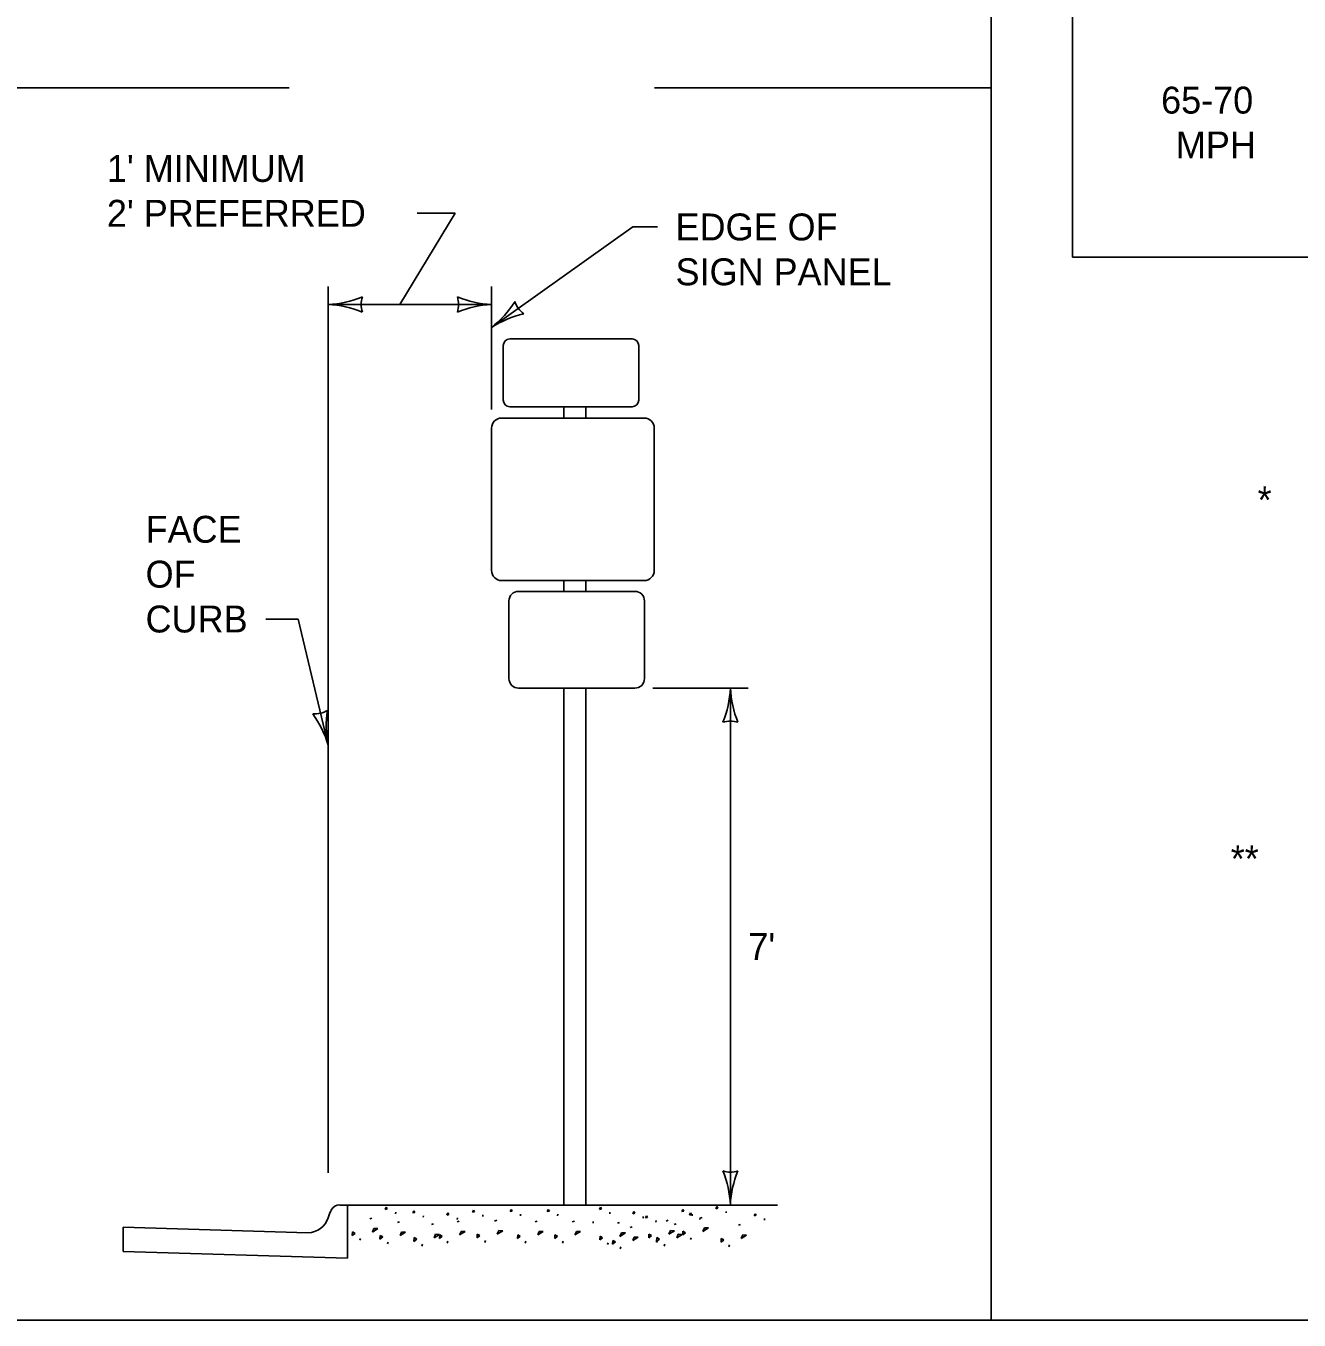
# Model space of a CAD drawing. Extents: x 49991.4 to 50021, y 49987.6 to 50011.4.
# Drawn here: x 50005.916 to 50008.753, y 49987.799 to 49990.684 of the extents above; entities that cross this region are included whole.
import ezdxf

# ---------------------------------------------------------------- set-up
doc = ezdxf.new("R2010")
doc.units = 0
for name, color, linetype in [('Level 1', 7, 'Continuous'), ('Level 2', 7, 'Continuous'), ('Level 3', 7, 'Continuous')]:
    doc.layers.add(name, color=color, linetype=linetype)

msp = doc.modelspace()

# ---------------------------------------------------------------- linework, layer by layer
at = {"layer": 'Level 1'}
for p, q in [((50006.9943, 49989.9861), (50007.2664, 49989.9861)), ((50006.9793, 49989.8499), (50006.9793, 49989.9711)), ((50007.2814, 49989.9711), (50007.2814, 49989.8499)), ((50007.2664, 49989.8349), (50006.9943, 49989.8349)), ((50007.1148, 49989.8098), (50007.1148, 49989.8349)), ((50007.1634, 49989.8098), (50007.1634, 49989.8349)), ((50006.9534, 49989.4698), (50006.9534, 49989.7873)), ((50006.9759, 49989.8098), (50007.2935, 49989.8098)), ((50007.316, 49989.7873), (50007.316, 49989.4698)), ((50007.2935, 49989.4473), (50006.9759, 49989.4473)), ((50007.1148, 49989.4234), (50007.1148, 49989.4473)), ((50007.1634, 49989.4234), (50007.1634, 49989.4473)), ((50007.0136, 49989.4234), (50007.2728, 49989.4234)), ((50006.9921, 49989.229), (50006.9921, 49989.4019)), ((50007.2943, 49989.4019), (50007.2943, 49989.229)), ((50007.2728, 49989.2075), (50007.0136, 49989.2075)), ((50007.1148, 49988.0554), (50007.1148, 49989.2075)), ((50007.1634, 49988.0554), (50007.1634, 49989.2075)), ((50006.6326, 49988.0554), (50006.6156, 49988.0554)), ((50006.6326, 49988.0554), (50007.5908, 49988.0554)), ((50006.6326, 49987.9369), (50006.6326, 49988.0554)), ((50007.4531, 49988.0472), (50007.4551, 49988.0519)), ((50007.4551, 49988.0519), (50007.4575, 49988.0483)), ((50006.6866, 49988.0261), (50006.682, 49988.0245)), ((50006.7165, 49988.0456), (50006.7186, 49988.0503)), ((50006.721, 49988.0467), (50006.7165, 49988.0456)), ((50006.7186, 49988.0503), (50006.721, 49988.0467)), ((50006.7394, 49988.036), (50006.7399, 49988.0396)), ((50006.7781, 49988.0376), (50006.7802, 49988.0423)), ((50006.7826, 49988.0387), (50006.7781, 49988.0376)), ((50006.7802, 49988.0423), (50006.7826, 49988.0387)), ((50006.8011, 49988.028), (50006.8015, 49988.0316)), ((50006.8541, 49988.0328), (50006.8561, 49988.0376)), ((50006.8585, 49988.0339), (50006.8541, 49988.0328)), ((50006.8561, 49988.0376), (50006.8585, 49988.0339)), ((50006.877, 49988.0233), (50006.8775, 49988.0269)), ((50006.9109, 49988.0393), (50006.913, 49988.044)), ((50006.9154, 49988.0404), (50006.9109, 49988.0393)), ((50006.913, 49988.044), (50006.9154, 49988.0404)), ((50006.9339, 49988.0297), (50006.9343, 49988.0333)), ((50006.9947, 49988.0409), (50006.9968, 49988.0456)), ((50006.9992, 49988.0419), (50006.9947, 49988.0409)), ((50006.9968, 49988.0456), (50006.9992, 49988.0419)), ((50007.0177, 49988.0313), (50007.0181, 49988.0349)), ((50007.0777, 49988.0409), (50007.0798, 49988.0456)), ((50007.0822, 49988.0419), (50007.0777, 49988.0409)), ((50007.0798, 49988.0456), (50007.0822, 49988.0419)), ((50007.1007, 49988.0313), (50007.1011, 49988.0349)), ((50007.1939, 49988.0456), (50007.1959, 49988.0503)), ((50007.1984, 49988.0467), (50007.1939, 49988.0456)), ((50007.1959, 49988.0503), (50007.1984, 49988.0467)), ((50007.2168, 49988.036), (50007.2173, 49988.0396)), ((50007.2682, 49988.036), (50007.2703, 49988.0407)), ((50007.2727, 49988.0371), (50007.2682, 49988.036)), ((50007.2703, 49988.0407), (50007.2727, 49988.0371)), ((50007.2912, 49988.0264), (50007.2916, 49988.0301)), ((50007.2966, 49988.0265), (50007.2987, 49988.0313)), ((50007.3011, 49988.0276), (50007.2966, 49988.0265)), ((50007.2987, 49988.0313), (50007.3011, 49988.0276)), ((50007.3773, 49988.0409), (50007.3793, 49988.0456)), ((50007.3817, 49988.0419), (50007.3773, 49988.0409)), ((50007.3793, 49988.0456), (50007.3817, 49988.0419)), ((50007.3946, 49988.0328), (50007.3967, 49988.0376)), ((50007.3991, 49988.0339), (50007.3946, 49988.0328)), ((50007.3967, 49988.0376), (50007.3991, 49988.0339)), ((50007.4002, 49988.0313), (50007.4007, 49988.0349)), ((50007.4175, 49988.0233), (50007.418, 49988.0269)), ((50007.4231, 49988.0276), (50007.4185, 49988.0261)), ((50007.4575, 49988.0483), (50007.4531, 49988.0472)), ((50007.476, 49988.0376), (50007.4765, 49988.0412)), ((50007.5384, 49988.0313), (50007.5405, 49988.036)), ((50007.5429, 49988.0324), (50007.5384, 49988.0313)), ((50007.5405, 49988.036), (50007.5429, 49988.0324)), ((50007.5614, 49988.0217), (50007.5618, 49988.0253)), ((50006.5443, 49987.9937), (50006.1327, 49988.006)), ((50006.1327, 49988.006), (50006.1327, 49987.9518)), ((50006.6429, 49987.9871), (50006.6434, 49987.9954)), ((50006.6434, 49987.9954), (50006.6492, 49987.9921)), ((50006.6912, 49988.003), (50006.6879, 49987.9951)), ((50006.6879, 49987.9951), (50006.7, 49988.0028)), ((50006.7, 49988.0028), (50006.6912, 49988.003)), ((50006.7482, 49988.0181), (50006.7436, 49988.0165)), ((50006.7528, 49987.995), (50006.7495, 49987.9871)), ((50006.7495, 49987.9871), (50006.7616, 49987.9948)), ((50006.7616, 49987.9948), (50006.7528, 49987.995)), ((50006.8241, 49988.0133), (50006.8195, 49988.0117)), ((50006.881, 49988.0197), (50006.8764, 49988.0182)), ((50006.8856, 49987.9967), (50006.8823, 49987.9888)), ((50006.8823, 49987.9888), (50006.8944, 49987.9965)), ((50006.8944, 49987.9965), (50006.8856, 49987.9967)), ((50006.9648, 49988.0213), (50006.9602, 49988.0197)), ((50006.9694, 49987.9983), (50006.9661, 49987.9904)), ((50006.9661, 49987.9904), (50006.9782, 49987.998)), ((50006.9782, 49987.998), (50006.9694, 49987.9983)), ((50007.0549, 49988.0197), (50007.0503, 49988.0182)), ((50007.0595, 49987.9967), (50007.0562, 49987.9888)), ((50007.0562, 49987.9888), (50007.0684, 49987.9965)), ((50007.0684, 49987.9965), (50007.0595, 49987.9967)), ((50007.1379, 49988.0197), (50007.1333, 49988.0182)), ((50007.1425, 49987.9967), (50007.1392, 49987.9888)), ((50007.1392, 49987.9888), (50007.1514, 49987.9965)), ((50007.1514, 49987.9965), (50007.1425, 49987.9967)), ((50007.1797, 49988.0151), (50007.1801, 49988.0187)), ((50007.2383, 49988.0165), (50007.2337, 49988.0149)), ((50007.2429, 49987.9934), (50007.2396, 49987.9855)), ((50007.2396, 49987.9855), (50007.2517, 49987.9932)), ((50007.2517, 49987.9932), (50007.2429, 49987.9934)), ((50007.2667, 49988.007), (50007.262, 49988.0054)), ((50007.3195, 49988.017), (50007.32, 49988.0206)), ((50007.3473, 49988.0213), (50007.3427, 49988.0197)), ((50007.3519, 49987.9983), (50007.3486, 49987.9904)), ((50007.3486, 49987.9904), (50007.3608, 49987.998)), ((50007.3608, 49987.998), (50007.3519, 49987.9983)), ((50007.3646, 49988.0133), (50007.36, 49988.0117)), ((50007.3794, 49987.9887), (50007.3799, 49987.9969)), ((50007.3857, 49987.9937), (50007.3794, 49987.9887)), ((50007.3799, 49987.9969), (50007.3857, 49987.9937)), ((50007.4277, 49988.0046), (50007.4244, 49987.9967)), ((50007.4244, 49987.9967), (50007.4366, 49988.0043)), ((50007.4366, 49988.0043), (50007.4277, 49988.0046)), ((50007.5085, 49988.0117), (50007.5039, 49988.0102)), ((50006.6492, 49987.9921), (50006.6429, 49987.9871)), ((50006.6617, 49987.9809), (50006.6601, 49987.9767)), ((50006.7045, 49987.9791), (50006.705, 49987.9874)), ((50006.7108, 49987.9841), (50006.7045, 49987.9791)), ((50006.705, 49987.9874), (50006.7108, 49987.9841)), ((50006.7233, 49987.9729), (50006.7217, 49987.9687)), ((50006.7804, 49987.9744), (50006.7809, 49987.9826)), ((50006.7867, 49987.9794), (50006.7804, 49987.9744)), ((50006.7809, 49987.9826), (50006.7867, 49987.9794)), ((50006.7992, 49987.9682), (50006.7977, 49987.964)), ((50006.8287, 49987.9903), (50006.8254, 49987.9824)), ((50006.8254, 49987.9824), (50006.8376, 49987.99)), ((50006.8376, 49987.99), (50006.8287, 49987.9903)), ((50006.8373, 49987.9808), (50006.8378, 49987.9891)), ((50006.8436, 49987.9858), (50006.8373, 49987.9808)), ((50006.8378, 49987.9891), (50006.8436, 49987.9858)), ((50006.8561, 49987.9746), (50006.8545, 49987.9704)), ((50006.9211, 49987.9824), (50006.9216, 49987.9906)), ((50006.9274, 49987.9874), (50006.9211, 49987.9824)), ((50006.9216, 49987.9906), (50006.9274, 49987.9874)), ((50006.9399, 49987.9762), (50006.9383, 49987.972)), ((50007.0112, 49987.9808), (50007.0117, 49987.9891)), ((50007.0175, 49987.9858), (50007.0112, 49987.9808)), ((50007.0117, 49987.9891), (50007.0175, 49987.9858)), ((50007.03, 49987.9746), (50007.0285, 49987.9704)), ((50007.0942, 49987.9808), (50007.0947, 49987.9891)), ((50007.1005, 49987.9858), (50007.0942, 49987.9808)), ((50007.0947, 49987.9891), (50007.1005, 49987.9858)), ((50007.113, 49987.9746), (50007.1115, 49987.9704)), ((50007.1946, 49987.9775), (50007.1951, 49987.9858)), ((50007.2009, 49987.9825), (50007.1946, 49987.9775)), ((50007.1951, 49987.9858), (50007.2009, 49987.9825)), ((50007.2134, 49987.9714), (50007.2118, 49987.9671)), ((50007.223, 49987.9681), (50007.2235, 49987.9763)), ((50007.2293, 49987.9731), (50007.223, 49987.9681)), ((50007.2235, 49987.9763), (50007.2293, 49987.9731)), ((50007.2713, 49987.984), (50007.268, 49987.9761)), ((50007.268, 49987.9761), (50007.2801, 49987.9837)), ((50007.2801, 49987.9837), (50007.2713, 49987.984)), ((50007.3036, 49987.9824), (50007.3041, 49987.9906)), ((50007.3099, 49987.9874), (50007.3036, 49987.9824)), ((50007.3041, 49987.9906), (50007.3099, 49987.9874)), ((50007.3224, 49987.9762), (50007.3209, 49987.972)), ((50007.321, 49987.9744), (50007.3215, 49987.9826)), ((50007.3273, 49987.9794), (50007.321, 49987.9744)), ((50007.3215, 49987.9826), (50007.3273, 49987.9794)), ((50007.3398, 49987.9682), (50007.3382, 49987.964)), ((50007.3693, 49987.9903), (50007.366, 49987.9824)), ((50007.366, 49987.9824), (50007.3781, 49987.99)), ((50007.3781, 49987.99), (50007.3693, 49987.9903)), ((50007.3982, 49987.9825), (50007.3967, 49987.9783)), ((50007.4648, 49987.9728), (50007.4653, 49987.9811)), ((50007.4711, 49987.9778), (50007.4648, 49987.9728)), ((50007.4653, 49987.9811), (50007.4711, 49987.9778)), ((50007.4836, 49987.9666), (50007.482, 49987.9624)), ((50007.5131, 49987.9887), (50007.5098, 49987.9808)), ((50007.5098, 49987.9808), (50007.5219, 49987.9885)), ((50007.5219, 49987.9885), (50007.5131, 49987.9887)), ((50006.1327, 49987.9518), (50006.6326, 49987.9369)), ((50007.2418, 49987.9619), (50007.2402, 49987.9577))]:
    msp.add_line(p, q, dxfattribs=at)
msp.add_lwpolyline([(49999.3835, 49998.9992), (50016.7501, 49998.9992), (50016.7501, 49987.7988), (49999.3835, 49987.7988)], close=True, dxfattribs=at)
for centre, radius, start, end in [((50006.9943, 49989.9711), 0.015, 90, 180), ((50007.2664, 49989.9711), 0.015, 0, 90), ((50006.9943, 49989.8499), 0.015, 180, 270), ((50007.2664, 49989.8499), 0.015, 270, 0), ((50006.9759, 49989.7873), 0.0225, 90, 180), ((50007.2935, 49989.7873), 0.0225, 0, 90), ((50006.9759, 49989.4698), 0.0225, 180, 270), ((50007.2935, 49989.4698), 0.0225, 270, 0), ((50007.0136, 49989.4019), 0.0215, 90, 180), ((50007.2728, 49989.4019), 0.0215, 0, 90), ((50007.0136, 49989.229), 0.0215, 180, 270), ((50007.2728, 49989.229), 0.0215, 270, 0), ((50006.614, 49988.0361), 0.0194, 85.2999, 156.6889), ((50006.5439, 49988.0414), 0.0477, 270.4937, 342.4535), ((50006.6403, 49988.0161), 0.0521, 148.3066, 167.8949)]:
    msp.add_arc(centre, radius, start, end, dxfattribs=at)
at = {"layer": 'Level 2'}
for p, q in [((50008.2479, 49993.5684), (50008.2479, 49990.1684)), ((50008.2479, 49990.1684), (50013.0279, 49990.1684))]:
    msp.add_line(p, q, dxfattribs=at)
at = {"layer": 'Level 3'}
for p, q in [((50008.0668, 49994.0732), (50008.0668, 49987.7988)), ((50005.0025, 49990.5461), (50006.5025, 49990.5461)), ((50008.0668, 49990.5461), (50007.3168, 49990.5461)), ((50006.7488, 49990.0628), (50006.8726, 49990.2661)), ((50006.8726, 49990.2661), (50006.7877, 49990.2661)), ((50006.9534, 49990.0117), (50007.268, 49990.2357)), ((50007.268, 49990.2357), (50007.3234, 49990.2357)), ((50006.5894, 49988.127), (50006.5894, 49990.1028)), ((50006.9534, 49989.8286), (50006.9534, 49990.1028)), ((50006.5894, 49990.0628), (50006.9534, 49990.0628)), ((50006.4506, 49989.3617), (50006.5226, 49989.3617)), ((50006.5226, 49989.3617), (50006.5894, 49989.0802)), ((50007.3128, 49989.2075), (50007.5256, 49989.2075)), ((50007.4856, 49988.0554), (50007.4856, 49989.2075))]:
    msp.add_line(p, q, dxfattribs=at)
for centre, radius, start, end in [((50006.5779, 49990.2955), 0.233, 272.8273, 292.0772), ((50006.7176, 49990.0628), 0.0548, 162.1388, 197.8612), ((50006.9626, 49990.2849), 0.2223, 247.456, 267.6395), ((50006.8252, 49990.0628), 0.0548, 342.1388, 17.8612), ((50006.5802, 49989.8407), 0.2223, 67.456, 87.6395), ((50006.9649, 49989.8301), 0.233, 92.8273, 112.0772), ((50006.8091, 49990.1946), 0.233, 308.281, 327.5309), ((50007.0748, 49989.8254), 0.2223, 102.9097, 123.0932), ((50007.0578, 49990.086), 0.0548, 197.5925, 233.3149), ((50007.2635, 49989.2167), 0.2223, 337.456, 357.6395), ((50007.7183, 49989.219), 0.233, 182.8273, 202.0772), ((50006.559, 49989.2048), 0.0548, 265.8498, 301.5721), ((50006.366, 49989.0139), 0.233, 16.5382, 35.7881), ((50006.8074, 49989.124), 0.2223, 171.1669, 191.3505), ((50007.4856, 49989.0793), 0.0548, 72.1388, 107.8612), ((50007.4856, 49988.1836), 0.0548, 252.1388, 287.8612), ((50007.2529, 49988.0439), 0.233, 2.8273, 22.0772), ((50007.7077, 49988.0462), 0.2223, 157.456, 177.6395)]:
    msp.add_arc(centre, radius, start, end, dxfattribs=at)

# ---------------------------------------------------------------- texts
at = {"layer": 'Level 2'}
for s, p in [('65-70', (50008.4455, 49990.4884)), ('MPH', (50008.4784, 49990.3884)), ("1' MINIMUM", (50006.0962, 49990.3361)), ("2' PREFERRED", (50006.0962, 49990.2361)), ('EDGE OF', (50007.3634, 49990.2057)), ('SIGN PANEL', (50007.3634, 49990.1057)), ('*', (50008.6606, 49989.5972)), ('FACE', (50006.1824, 49989.5317)), ('OF', (50006.1824, 49989.4317)), ('CURB', (50006.1824, 49989.3317)), ('**', (50008.6006, 49988.7972)), ("7'", (50007.5256, 49988.6014))]:
    msp.add_text(s, height=0.06, dxfattribs=at).set_placement(p)

doc.saveas('drawing.dxf')
